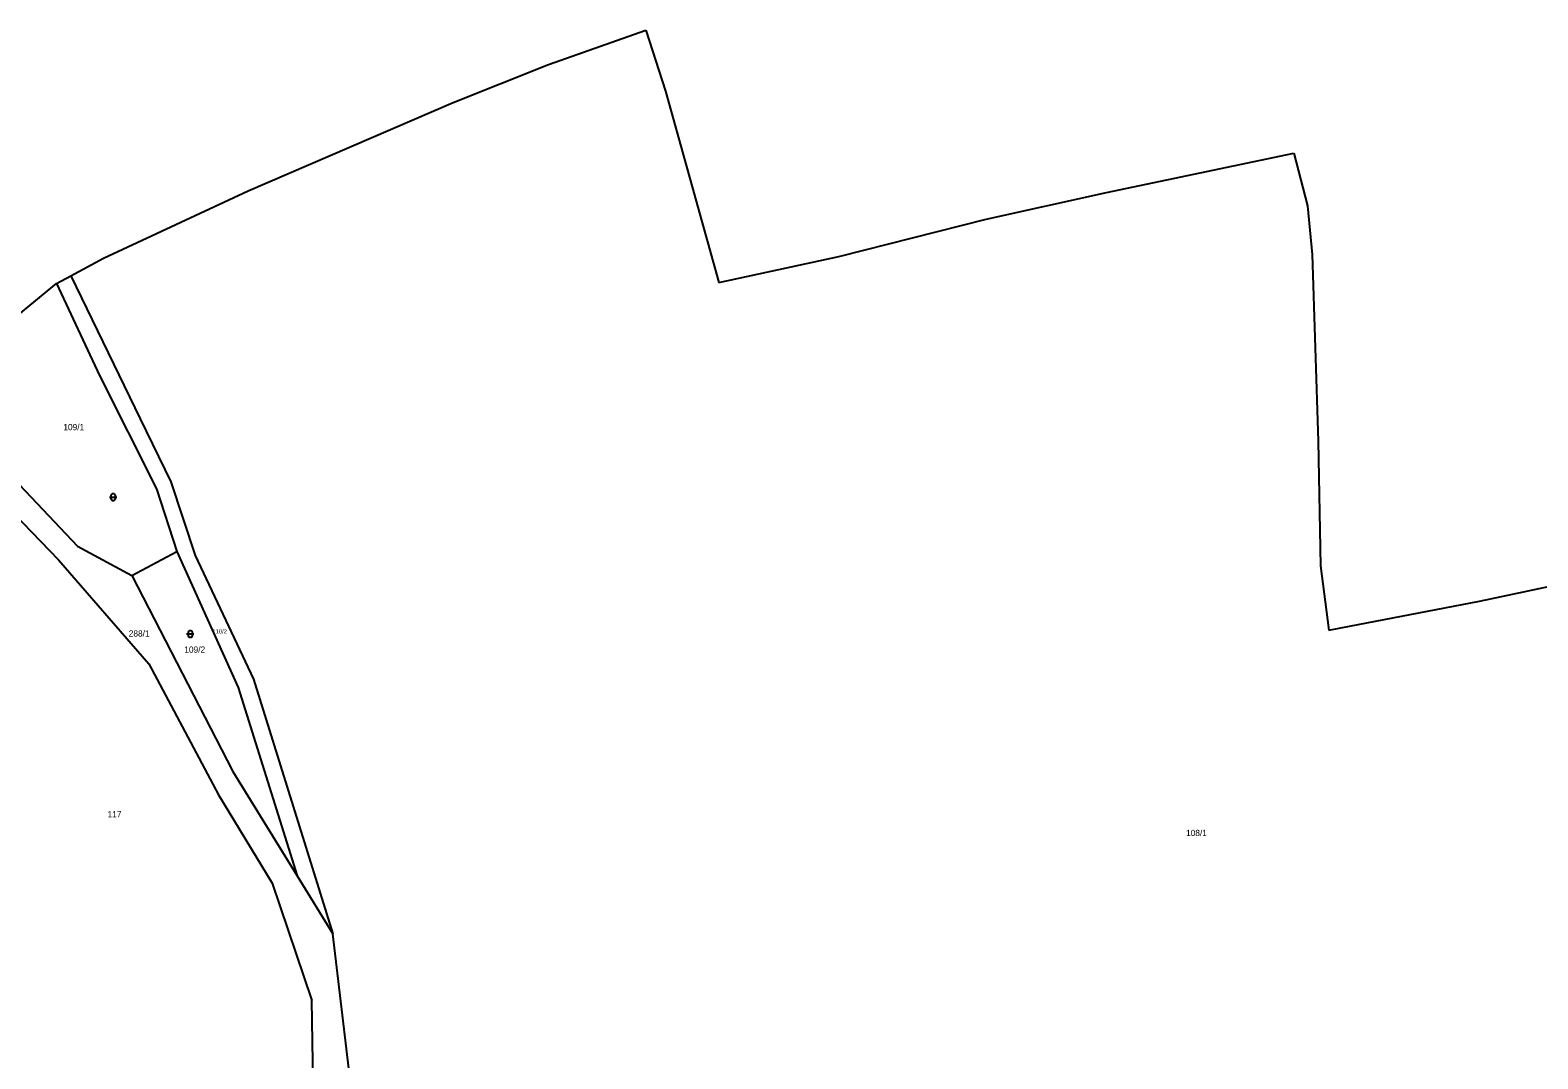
# Model space of a CAD drawing. Extents: x -780000 to -777378, y -1011169 to -1009297.
# Drawn here: x -779077.9 to -778666.9, y -1009880.5 to -1009600.2 of the extents above; entities that cross this region are included whole.
import ezdxf

# ---------------------------------------------------------------- set-up
doc = ezdxf.new("R2010")
doc.units = 0
for name, color, linetype in [('Default', 7, 'Continuous'), ('KN_HRANICE', 7, 'Continuous'), ('KN_KULTURY', 7, 'Continuous'), ('KN_PARCELY', 7, 'Continuous')]:
    doc.layers.add(name, color=color, linetype=linetype)

# ---------------------------------------------------------------- blocks, each defined once
blk = doc.blocks.new('316')
at = {"layer": 'Default'}
for points in [[(-1, 1), (0.27, 1), (1, 1)], [(-0.5, 1.5), (-0.4, 1.79), (-0.15, 1.97), (0.16, 1.97), (0.41, 1.79), (0.51, 1.5), (0.51, 0.5), (0.41, 0.21), (0.16, 0.03), (-0.15, 0.03), (-0.4, 0.21), (-0.5, 0.5), (-0.5, 1.5)]]:
    blk.add_lwpolyline(points, dxfattribs=at)

msp = doc.modelspace()

# ---------------------------------------------------------------- linework, layer by layer
at = {"layer": 'KN_HRANICE'}
for p, q in [((-778936.53, -1009609.5), (-778909.99, -1009600.16)), ((-778909.99, -1009600.16), (-778904.63, -1009616.78)), ((-778962.51, -1009619.84), (-778936.53, -1009609.5)), ((-779018.41, -1009643.9), (-778962.51, -1009619.84)), ((-778904.63, -1009616.78), (-778890.1, -1009668.94)), ((-778784.46, -1009644.35), (-778733.39, -1009633.72)), ((-778733.39, -1009633.72), (-778729.66, -1009648.02)), ((-779057.84, -1009662.28), (-779018.41, -1009643.9)), ((-778817.24, -1009651.68), (-778784.46, -1009644.35)), ((-778729.66, -1009648.02), (-778728.4, -1009661.25)), ((-778857.42, -1009661.85), (-778817.24, -1009651.68)), ((-778890.1, -1009668.94), (-778857.42, -1009661.85)), ((-778728.4, -1009661.25), (-778726.75, -1009712.18)), ((-779066.81, -1009667.14), (-779057.84, -1009662.28)), ((-779104.16, -1009696.65), (-779070.64, -1009669.21)), ((-779070.64, -1009669.21), (-779066.81, -1009667.14)), ((-779070.64, -1009669.21), (-779058.97, -1009694.24)), ((-779066.81, -1009667.14), (-779047.84, -1009706.06)), ((-779058.97, -1009694.24), (-779043.46, -1009725.16)), ((-779105.59, -1009697.82), (-779064.98, -1009740.75)), ((-779110.78, -1009702.44), (-779070.14, -1009744.53)), ((-779047.84, -1009706.06), (-779039.47, -1009723.23)), ((-778726.75, -1009712.18), (-778726.11, -1009746.11)), ((-779039.47, -1009723.23), (-779032.85, -1009743.31)), ((-779043.46, -1009725.16), (-779037.88, -1009742.18)), ((-779064.98, -1009740.75), (-779050.17, -1009748.78)), ((-779050.17, -1009748.78), (-779037.88, -1009742.18)), ((-779037.88, -1009742.18), (-779021.19, -1009779.25)), ((-779032.85, -1009743.31), (-779016.97, -1009776.97)), ((-779070.14, -1009744.53), (-779045.49, -1009772.81)), ((-778726.11, -1009746.11), (-778723.83, -1009763.64)), ((-779050.17, -1009748.78), (-779022.62, -1009802.17)), ((-778682.79, -1009755.72), (-778650.92, -1009748.98)), ((-778718.16, -1009762.55), (-778682.79, -1009755.72)), ((-778723.83, -1009763.64), (-778718.16, -1009762.55)), ((-779045.49, -1009772.81), (-779026.51, -1009808.52)), ((-779016.97, -1009776.97), (-778995.32, -1009846.4)), ((-779021.19, -1009779.25), (-779005.09, -1009830.57)), ((-779022.62, -1009802.17), (-779005.09, -1009830.57)), ((-779026.51, -1009808.52), (-779011.87, -1009832.55)), ((-779011.87, -1009832.55), (-779001.1, -1009864.61)), ((-779005.09, -1009830.57), (-778995.32, -1009846.4)), ((-778990.51, -1009886.89), (-778995.32, -1009846.4)), ((-779000.69, -1009886.92), (-779001.1, -1009864.61))]:
    msp.add_line(p, q, dxfattribs=at)

# ---------------------------------------------------------------- block references
at = {"layer": 'KN_KULTURY'}
for p in [(-779055.24, -1009728.42), (-779034.2, -1009765.67)]:
    msp.add_blockref('316', p, dxfattribs=at)

# ---------------------------------------------------------------- texts
at = {"layer": 'KN_PARCELY'}
for s, height, p in [('109/1', 1.7, (-779068.82, -1009709.17)), ('288/1', 1.7, (-779050.99, -1009765.39)), ('110/2', 1.14, (-779028.17, -1009764.56)), ('109/2', 1.7, (-779035.84, -1009769.8)), ('117', 1.7, (-779056.77, -1009814.67)), ('108/1', 1.7, (-778762.76, -1009819.76))]:
    msp.add_text(s, height=height, dxfattribs=at).set_placement(p)

doc.saveas('drawing.dxf')
